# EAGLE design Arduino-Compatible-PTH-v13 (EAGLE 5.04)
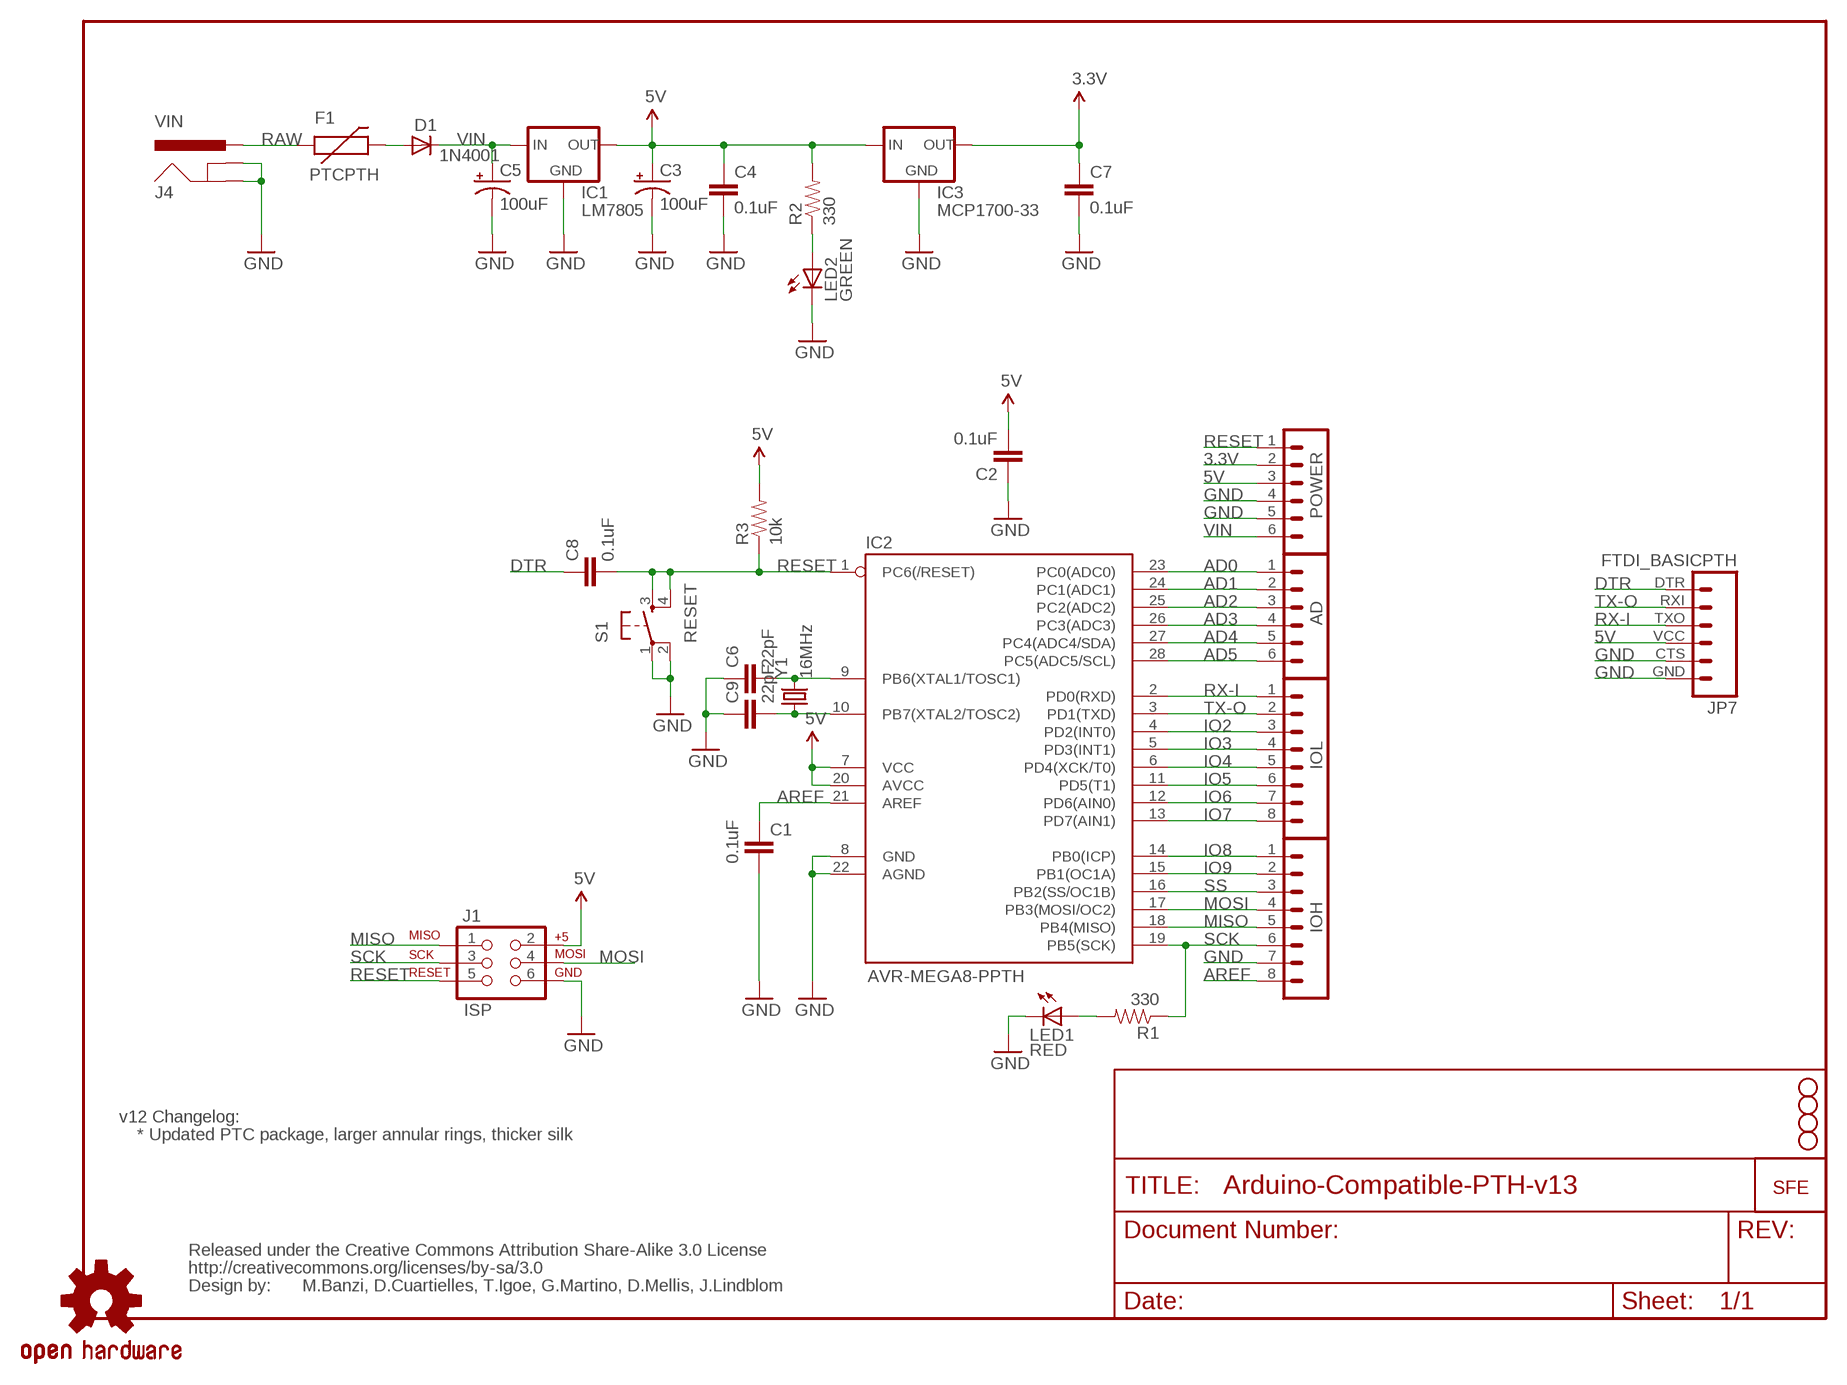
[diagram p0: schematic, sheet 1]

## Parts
AD  M06SIP  [1X06]
C1  0.1uF  CAPPTH2  [CAP-PTH-SMALL2]
C2  0.1uF  CAPPTH2  [CAP-PTH-SMALL2]
C3  100uF  CAP_POLPTH1  [CPOL-RADIAL-100UF-25V]
C4  0.1uF  CAPPTH2  [CAP-PTH-SMALL2]
C5  100uF  CAP_POLPTH1  [CPOL-RADIAL-100UF-25V]
C6  22pF  CAPPTH2  [CAP-PTH-SMALL2]
C7  0.1uF  CAPPTH2  [CAP-PTH-SMALL2]
C8  0.1uF  CAPPTH2  [CAP-PTH-SMALL2]
C9  22pF  CAPPTH2  [CAP-PTH-SMALL2]
D1  1N4001  DIODEPTH  [DIODE-1N4001]
F1  PTCPTH  [PTC]
IC1  LM7805  V_REG_78XX-TO-220  [TO-220-ALT]
IC2  AVR-MEGA8-PPTH  [DIL28-3]
IC3  MCP1700-33  V_REG_78XXTO-92  [TO-92]
IOH  M081X08  [1X08]
IOL  M081X08  [1X08]
J1  ISP  AVR_SPI_PRG_6PTH  [2X3]
J4  VIN  POWER_JACKPTH_LOCK  [POWER_JACK_PTH_LOCK]
JP1  LOGO-SFENEW  [SFE-NEW-WEBLOGO]
JP3  STAND-OFF  [STAND-OFF]
JP4  STAND-OFF  [STAND-OFF]
JP5  STAND-OFF  [STAND-OFF]
JP6  STAND-OFF  [STAND-OFF]
JP7  FTDI_BASICPTH  [FTDI_BASIC]
LED1  RED  LED5MM  [LED5MM]
LED2  GREEN  LED5MM  [LED5MM]
POWER  M06SIP  [1X06]
R1  330  RESISTORAXIAL-0.3  [AXIAL-0.3]
R2  330  RESISTORAXIAL-0.3  [AXIAL-0.3]
R3  10k  RESISTORAXIAL-0.3  [AXIAL-0.3]
S1  RESET  TAC_SWITCHPTH  [TACTILE-PTH]
U$7  OSHW-LOGOM  [OSHW-LOGO-M]
U$15  CREATIVE_COMMONS  [CREATIVE_COMMONS]
Y1  16MHz  CRYSTALHC49US  [HC49US]

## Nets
3.3V: C7.1 IC3.3(OUT) POWER.2
5V: C2.2 C3.1(+) C4.1 IC1.OUT IC2.7(VCC) IC2.20(AVCC) IC3.2(IN) J1.2 JP7.VCC POWER.3 R2.P$2 R3.P$2
AD0: AD.1 IC2.23(PC0(ADC0))
AD1: AD.2 IC2.24(PC1(ADC1))
AD2: AD.3 IC2.25(PC2(ADC2))
AD3: AD.4 IC2.26(PC3(ADC3))
AD4: AD.5 IC2.27(PC4(ADC4/SDA))
AD5: AD.6 IC2.28(PC5(ADC5/SCL))
AREF: C1.1 IC2.21(AREF) IOH.8
DTR: C8.1 JP7.DTR
GND: C1.2 C2.1 C3.2(-) C4.2 C5.2(-) C6.1 C7.2 C9.1 IC1.GND IC2.8(GND) IC2.22(AGND) IC3.1(GND) IOH.7 J1.6 J4.GND J4.GNDBREAK JP7.CTS JP7.GND LED1.K(C) LED2.K(C) POWER.4 POWER.5 S1.1 S1.2
IO2: IC2.4(PD2(INT0)) IOL.3
IO3: IC2.5(PD3(INT1)) IOL.4
IO4: IC2.6(PD4(XCK/T0)) IOL.5
IO5: IC2.11(PD5(T1)) IOL.6
IO6: IC2.12(PD6(AIN0)) IOL.7
IO7: IC2.13(PD7(AIN1)) IOL.8
IO8: IC2.14(PB0(ICP)) IOH.1
IO9: IC2.15(PB1(OC1A)) IOH.2
MISO: IC2.18(PB4(MISO)) IOH.5 J1.1
MOSI: IC2.17(PB3(MOSI/OC2)) IOH.4 J1.4
N$1: LED1.A R1.P$2
N$2: LED2.A R2.P$1
N$3: C6.2 IC2.9(PB6(XTAL1/TOSC1)) Y1.2
N$4: C9.2 IC2.10(PB7(XTAL2/TOSC2)) Y1.1
N$6: D1.A F1.P$2
RAW: F1.P$1 J4.PWR
RESET: C8.2 IC2.1(PC6(/RESET)) J1.5 POWER.1 R3.P$1 S1.3 S1.4
RX-I: IC2.2(PD0(RXD)) IOL.1 JP7.TXO
SCK: IC2.19(PB5(SCK)) IOH.6 J1.3 R1.P$1
SS: IC2.16(PB2(SS/OC1B)) IOH.3
TX-O: IC2.3(PD1(TXD)) IOL.2 JP7.RXI
VIN: C5.1(+) D1.C IC1.IN POWER.6

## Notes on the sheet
- v12 Changelog:
- * Updated PTC package, larger annular rings, thicker silk
- M.Banzi, D.Cuartielles, T.Igoe, G.Martino, D.Mellis, J.Lindblom

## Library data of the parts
AD POWER = SparkFun:M06: Header 6 Standard 6-pin 0.1" header. Use with straight break away headers (SKU : PRT-00116), right angle break away headers (PRT-00553), swiss pins (PRT-00743), machine pins (PRT-00117), and female headers (PRT-00115). Molex polarized connector foot print use with SKU : PRT-08094 with associated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
C1 C2 C4 C6-C9 = SparkFun:CAP: Capacitor
C3 C5 = SparkFun:CAP_POL: Capacitor Polarized
D1 = SparkFun:DIODE: Diode
F1 = SparkFun:PTC: Resettable Fuse PTC
IC1 IC3 = SparkFun:V_REG_78XX: Voltage Regulator Standard 7805 5V regulator. IGO (Input Ground Output). Spark Fun Electronics SKU : COM-00107
IC2 = SparkFun:AVR-MEGA8-P: MICROCONTROLLER 8 Kbytes FLASH 1 kbytes SRAM 512 bytes EEPROM USART 4-channel 10 bit ADC 2-channel 8 bit ADC
IOH IOL = SparkFun:M08: Header 8 Standard 8-pin 0.1" header. Use with straight break away headers (SKU : PRT-00116), right angle break away headers (PRT-00553), swiss pins (PRT-00743), machine pins (PRT-00117), and female headers (PRT-00115).
J1 = SparkFun:AVR_SPI_PRG_6: AVR ISP 6 Pin This is the reduced ISP connector for AVR programming. Common on Arduino. This footprint will take up less PCB space and can be used with a 10-pin to 6-pin adapter such as SKU: BOB-08508
J4 = SparkFun:POWER_JACK: Power Jack This is the standard 5.5mm barrel jack for power. The PTH is the most common, proven, reliable, footprint. All others are experimental. The Slot footprint only works if the mill layer is transmitted to the PCB fab house so be warned. Spark Fun Electronics SKU : PRT-00119. Mating wall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
JP1 = SparkFun:LOGO-SFE: Spark Fun Electronics PCB Logo
JP3-JP6 = SparkFun:STAND-OFF: Stand Off
JP7 = SparkFun:FTDI_BASIC: FTDI Basic: 3.3V and 5V
LED1 LED2 = SparkFun:LED: LEDs
R1-R3 = SparkFun:RESISTOR: Resistor
S1 = SparkFun:TAC_SWITCH: Momentary Switch Button commonly used for reset or general input. Spark Fun Electronics SKU : COM-00097
U$7 = SparkFun:OSHW-LOGO: Open Source Hardware Logo This logo indicates the piece of hardware it is found on incorporates a OSHW license and/or adheres to the definition of open source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
U$15 = SparkFun:CREATIVE_COMMONS
Y1 = SparkFun:CRYSTAL: Crystals

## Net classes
0 default: width 0.152 mm, drill 0.305 mm, clearance 0.152 mm

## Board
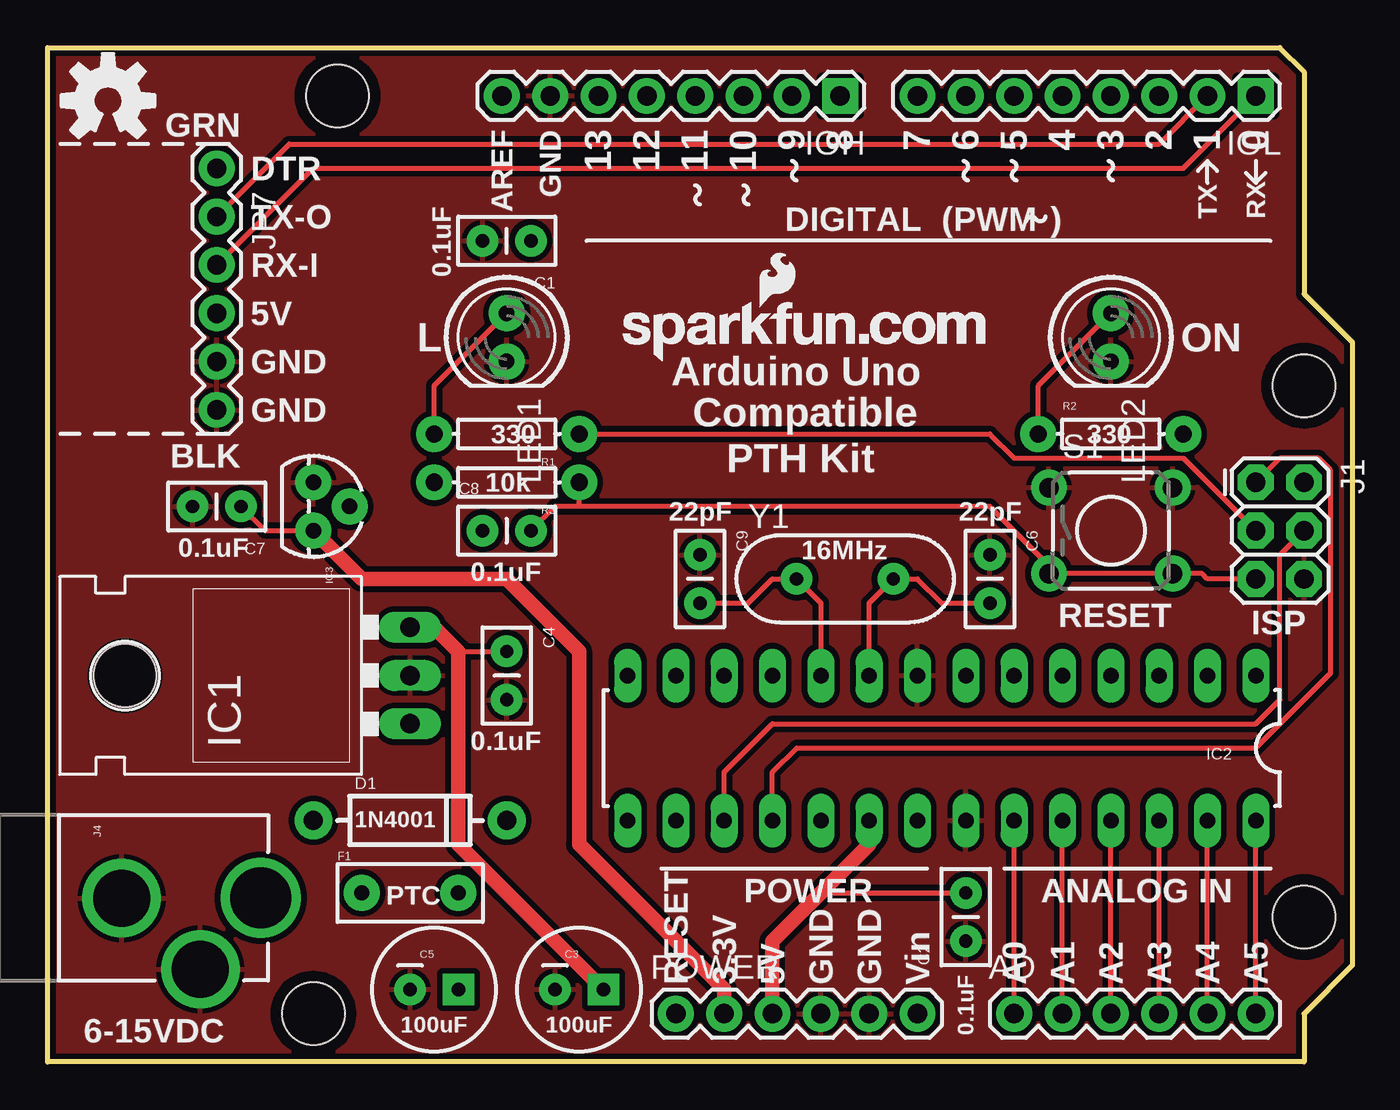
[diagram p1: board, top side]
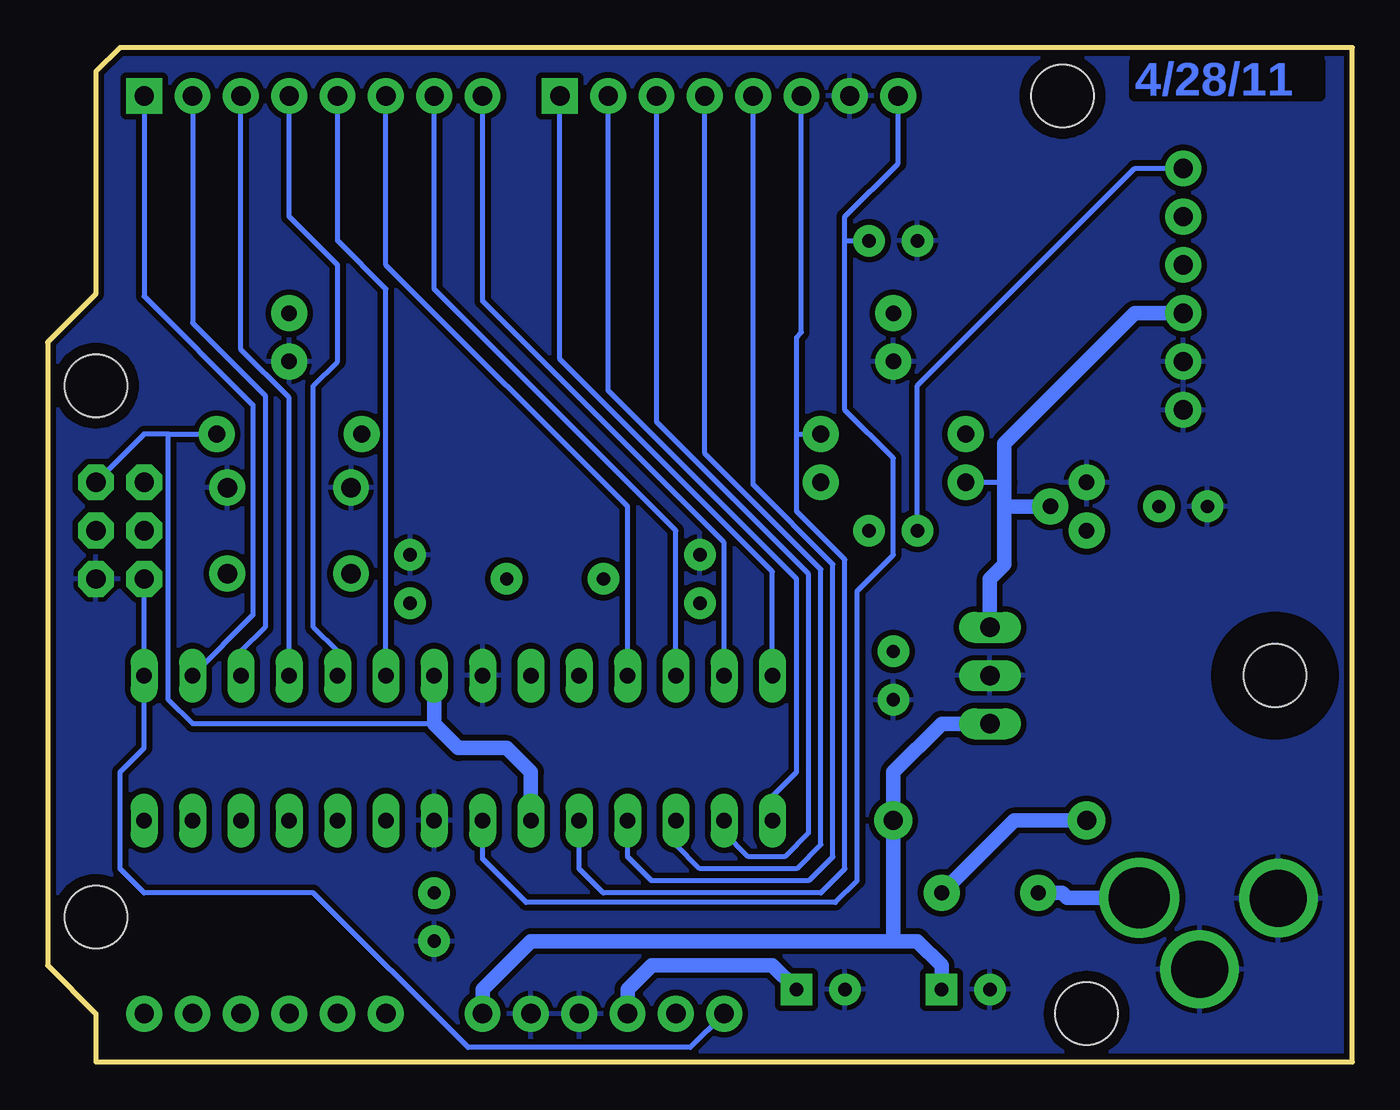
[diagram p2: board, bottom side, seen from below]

Size 68.58 x 53.34 mm. Coordinates in mm from the lower left corner, seen from the top.
Outline: 0,53.34 64.77,53.34 66.04,52.07 66.04,40.39 68.58,37.85 68.58,5.08 66.04,2.54 66.04,0 0,0 0,53.34
Copper layers (1*16): Top 0.035mm / dielectric 1.5mm / Bottom 0.035mm
Design rules "SparkFun *": minimum track width 8mil, minimum drill 20mil, track to track 8mil, track to pad 8mil, pad to pad 8mil, via to via 8mil, smd to smd 8mil, copper to edge 8mil, drill to drill 8mil, minimum pad ring 12mil, minimum via ring 10mil, stop-mask expansion 4mil, vias tented up to drill 20mil, thermal gap 10mil

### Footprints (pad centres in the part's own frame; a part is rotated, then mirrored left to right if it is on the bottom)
1X06 = drill 1.016 pad 1.88 round: 1 0,0; 2 2.54,0; 3 5.08,0; 4 7.62,0; 5 10.16,0; 6 12.7,0
CAP-PTH-SMALL2 = drill 0.7 pad 1.651 round: 1 0,0; 2 2.54,0
CPOL-RADIAL-100UF-25V = drill 0.7 pad 1.651 square: 1 1.27,0 | drill 0.7 pad 1.651 round: 2 -1.27,0
DIODE-1N4001 = drill 1 pad 1.981 round: A -5.08,0; C 5.08,0
PTC = drill 0.8 pad 1.88 round: P$1 -2.54,0; P$2 2.54,0
TO-220-ALT = drill 1.016 long: GND 0,-3.81; IN -2.54,-3.81; OUT 2.54,-3.81 | hole 3.302: 0,11.176
DIL28-3 = drill 0.813 long: 1 -16.51,-3.81; 2 -13.97,-3.81; 3 -11.43,-3.81; 4 -8.89,-3.81; 5 -6.35,-3.81; 6 -3.81,-3.81; 7 -1.27,-3.81; 8 1.27,-3.81; 9 3.81,-3.81; 10 6.35,-3.81; 11 8.89,-3.81; 12 11.43,-3.81; 13 13.97,-3.81; 14 16.51,-3.81; 15 16.51,3.81; 16 13.97,3.81; 17 11.43,3.81; 18 8.89,3.81; 19 6.35,3.81; 20 3.81,3.81; 21 1.27,3.81; 22 -1.27,3.81; 23 -3.81,3.81; 24 -6.35,3.81; 25 -8.89,3.81; 26 -11.43,3.81; 27 -13.97,3.81; 28 -16.51,3.81
TO-92 = drill 0.813 pad 1.88 round: 1 -1.27,0; 2 0,1.905; 3 1.27,0
1X08 = drill 1.016 pad 1.88 square: 1 0,0 | drill 1.016 pad 1.88 round: 2 2.54,0; 3 5.08,0; 4 7.62,0; 5 10.16,0; 6 12.7,0; 7 15.24,0; 8 17.78,0
2X3 = drill 1.016 pad 1.88 octagon: 1 0,0; 2 0,2.54; 3 2.54,0; 4 2.54,2.54; 5 5.08,0; 6 5.08,2.54
POWER_JACK_PTH_LOCK = drill 2.997 pad 4.115 round: GND 0.025,6.557; GNDBREAK 3.762,10.7 | drill 3.2 pad 4.115 round: PWR 0,13.878
STAND-OFF = hole 3.302: 0,0
FTDI_BASIC = drill 1.016 pad 1.88 round: CTS 10.16,0; DTR 0,0; GND 12.7,0; RXI 2.54,0; TXO 5.08,0; VCC 7.62,0
LED5MM = drill 0.813 pad 1.88 round: A -1.27,0; K 1.27,0
AXIAL-0.3 = drill 0.9 pad 1.88 round: P$1 -3.81,0; P$2 3.81,0
TACTILE-PTH = drill 1.016 pad 1.88 round: 1 -3.251,2.261; 2 3.251,2.261; 3 -3.251,-2.261; 4 3.251,-2.261
HC49US = drill 0.7 pad 1.651 round: 1 -2.54,0; 2 2.54,0

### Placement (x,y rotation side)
AD  50.8,2.54 0 top
C1  25.4,43.18 180 top
C2  48.26,6.35 90 top
C3  27.94,3.81 0 top
C4  24.13,21.59 270 top
C5  20.32,3.81 0 top
C6  49.53,26.67 270 top
C7  10.16,29.21 180 top
C8  22.86,27.94 0 top
C9  34.29,26.67 270 top
D1  19.05,12.7 0 top
F1  19.05,8.89 0 top
IC1  15.24,20.32 90 top
IC2  46.99,16.51 180 top
IC3  13.97,29.21 270 top
IOH  41.66,50.8 180 top
IOL  63.5,50.8 180 top
J1  63.5,30.48 270 top
J4  -2.67,8.64 270 top
JP1  30.23,36.83 0 top
JP3  13.97,2.54 0 top
JP4  66.04,7.62 0 top
JP5  66.04,35.56 0 top
JP6  15.24,50.8 0 top
JP7  8.89,46.99 270 top
LED1  24.13,38.1 270 top
LED2  55.88,38.1 270 top
POWER  33.02,2.54 0 top
R1  24.13,33.02 180 top
R2  55.88,33.02 0 top
R3  24.13,30.48 180 top
S1  55.88,27.94 0 top
U$7  3.17,50.55 0 top
U$15  not placed on the board
Y1  41.91,25.4 0 top

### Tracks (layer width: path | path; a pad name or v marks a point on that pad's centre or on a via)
3.3V
  Top 0.254: C7.1 11.43,27.94 IC3.3
  Top 0.762: POWER.2 35.56,3.81 27.94,11.43 27.94,21.59 24.13,25.4 16.51,25.4 IC3.3
5V
  Top 0.254: 40.64,8.89 C2.2 | 21.59,21.59 C4.1
  Top 0.762: IC1.OUT 20.32,22.86 21.59,21.59 21.59,11.43 C3.1 | IC2.20 43.18,11.43 40.64,8.89 38.1,6.35 POWER.3
  Bottom 0.254: 48.26,17.78 60.96,17.78 62.23,19.05 62.23,33.02 | 62.23,33.02 R2.P$2 | 62.23,33.02 63.5,33.02 J1.2 | 18.29,30.48 R3.P$2
  Bottom 0.762: POWER.3 38.1,3.81 36.83,5.08 30.48,5.08 C3.1 | IC2.20 43.18,15.24 44.45,16.51 46.99,16.51 48.26,17.78 IC2.7 | JP7.VCC 11.43,39.37 18.29,32.51 18.29,30.48 18.29,29.21 | IC1.OUT 19.05,25.4 18.29,26.16 18.29,29.21 | 18.29,29.21 IC3.2
AD0
  Top 0.254: AD.1 IC2.23
AD1
  Top 0.254: AD.2 IC2.24
AD2
  Top 0.254: AD.3 IC2.25
AD3
  Top 0.254: AD.4 IC2.26
AD4
  Top 0.254: AD.5 IC2.27
AD5
  Top 0.254: AD.6 IC2.28
AREF
  Bottom 0.254: IC2.21 45.72,10.67 43.43,8.38 27.18,8.38 26.04,9.53 26.04,24.77 24.13,26.67 24.13,31.75 26.67,34.29 26.67,43.18 | IOH.8 23.88,47.24 26.67,44.45 26.67,43.18 | 26.67,43.18 C1.1
DTR
  Bottom 0.254: C8.1 22.86,35.56 11.43,46.99 JP7.DTR
GND
  pour Bottom (isolate 0.305): 0,53.34 0,0 66.04,0 66.04,2.54 68.58,5.08 68.58,38.1 66.04,40.64 66.04,52.07 64.77,53.34
  pour Top (isolate 0.305): 0,53.34 0,0 66.04,0 66.04,2.54 68.58,5.08 68.58,38.1 66.04,40.64 66.04,52.07 64.77,53.34
IO2
  Bottom 0.254: IC2.4 55.88,34.92 58.42,37.47 IOL.3
IO3
  Bottom 0.254: IC2.5 53.34,21.59 54.61,22.86 54.61,35.56 53.34,36.83 53.34,41.91 55.88,44.45 IOL.4
IO4
  Bottom 0.254: IC2.6 50.8,40.64 53.34,43.18 IOL.5
IO5
  Bottom 0.254: IOL.6 50.8,41.91 38.1,29.21 IC2.11
IO6
  Bottom 0.254: IOL.7 48.26,40.64 35.56,27.94 IC2.12
IO7
  Bottom 0.254: IOL.8 45.72,40.01 33.02,27.3 IC2.13
IO8
  Bottom 0.254: IC2.14 30.48,25.78 41.66,36.96 IOH.1
IO9
  Bottom 0.254: IC2.15 30.48,13.97 29.21,15.24 29.21,25.4 39.12,35.31 IOH.2
MISO
  Top 0.254: J1.1 64.77,31.75 66.8,31.75 67.44,31.11 67.44,20.45 63.5,16.51 39.37,16.51 38.1,15.24 IC2.18
  Bottom 0.254: IC2.18 38.1,10.79 36.83,9.53 28.57,9.53 27.3,10.79 27.3,26.16 31.5,30.35 IOH.5
MOSI
  Top 0.254: IC2.17 35.56,15.24 38.1,17.78 63.5,17.78 64.77,19.05 64.77,26.67 J1.4
  Bottom 0.254: IOH.4 34.04,32 27.94,25.91 27.94,11.43 29.21,10.16 34.29,10.16 35.56,11.43 IC2.17
N$1
  Top 0.254: R1.P$2 20.32,35.56 LED1.A
N$2
  Top 0.254: R2.P$1 52.07,35.56 LED2.A
N$3
  Top 0.254: IC2.9 43.18,24.13 Y1.2 45.72,25.4 46.99,24.13 C6.2
N$4
  Top 0.254: IC2.10 40.64,24.13 Y1.1 38.1,25.4 36.83,24.13 C9.2
N$6
  Bottom 0.762: D1.A 17.78,12.7 F1.P$2
RAW
  Bottom 0.762: J4.PWR 14.99,8.64 15.24,8.89 F1.P$1
RESET
  Top 0.254: 27.94,29.21 R3.P$1 | J1.5 60.96,25.4 60.68,25.68 S1.4 S1.3 52.63,26.11 49.53,29.21 27.94,29.21 | 27.94,29.21 26.67,29.21 C8.2
  Bottom 0.254: POWER.1 34.8,0.76 46.48,0.76 54.61,8.89 63.5,8.89 64.77,10.16 64.77,15.24 63.5,16.51 IC2.1 J1.5
RX-I
  Top 0.254: JP7.TXO 13.97,46.99 59.69,46.99 IOL.1
  Bottom 0.254: IOL.1 63.5,40.26 57.78,34.54 57.78,23.5 IC2.2
SCK
  Top 0.254: J1.3 59.69,31.75 50.8,31.75 49.53,33.02 R1.P$1
  Bottom 0.254: IC2.19 40.64,10.16 39.37,8.89 27.94,8.89 26.67,10.16 26.67,26.42 29.21,28.96 29.21,33.02 | IOH.6 28.96,38.35 29.21,38.1 29.21,33.02 | 29.21,33.02 R1.P$1
SS
  Bottom 0.254: IOH.3 36.58,33.66 28.57,25.65 28.57,12.06 29.84,10.79 31.75,10.79 33.02,12.06 IC2.16
TX-O
  Top 0.254: JP7.RXI 12.7,48.26 58.42,48.26 IOL.2
  Bottom 0.254: IC2.3 58.42,21.59 57.15,22.86 57.15,35.05 60.96,38.86 IOL.2
VIN
  Bottom 0.762: C5.1 21.59,5.08 22.86,6.35 24.13,6.35 | POWER.6 45.72,3.81 43.18,6.35 24.13,6.35 | 24.13,6.35 D1.C 24.13,15.24 21.59,17.78 IC1.IN

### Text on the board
Bottom: 4/28/11
tPlace: GRN | AREF | GND | 13 | 12 | 11 | 10 | 9 | 8 | 7 | 6 | 5 | 4 | 3 | 2 | 1 | 0 | DTR | TX-O | DIGITAL | (PWM | ) | TX | RX | RX-I | 0.1uF | 5V | L | ON | GND | Arduino Uno | GND | BLK | Compatible | PTH Kit | 22pF | 22pF | 0.1uF | 16MHz | 0.1uF | RESET | ISP | 0.1uF | 1N4001 | PTC | POWER | ANALOG IN | RESET | 3.3V | 5V | GND | GND | Vin | A0 | A1 | A2 | A3 | A4 | A5 | 100uF | 100uF | 6-15VDC | 0.1uF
